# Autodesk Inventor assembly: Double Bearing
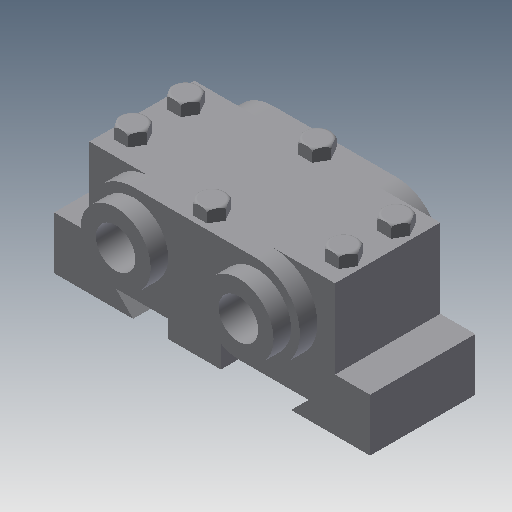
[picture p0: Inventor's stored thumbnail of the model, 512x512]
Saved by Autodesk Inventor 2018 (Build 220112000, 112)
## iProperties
Shininess: 64.0
Length Units: 11269
Angle Units: 11279
Time Units: 11290
Mass Units: 11283
Length Display Precision: 3
Angle Display Precision: 2
Created: 2002-02
Part Number: Double Bearing
Document SubType Name: Assembly
Designer: ***
Density: 0.0
Volumn: 0.0
Area: 0.0
PropertySet Name: Model Information
Control State: 0
Master: False
Checked Out: False
Author: ***
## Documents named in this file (5)
- E:\_Deepak\Inventor\Autodesk Inventor_2017_Project\Resources\Inventor_2017_tut\c12_Inv_tut_2017\c12_tut02_inv\Double Bearing.iam
- E:\_Deepak\Inventor\Autodesk Inventor_2017_Project\Resources\Inventor_2017_tut\c12_Inv_tut_2017\c12_tut02_inv\Base.ipt
- E:\_Deepak\Inventor\Autodesk Inventor_2017_Project\Resources\Inventor_2017_tut\c12_Inv_tut_2017\c12_tut02_inv\Cap.ipt
- E:\_Deepak\Inventor\Autodesk Inventor_2017_Project\Resources\Inventor_2017_tut\c12_Inv_tut_2017\c12_tut02_inv\Bushing.ipt
- E:\_Deepak\Inventor\Autodesk Inventor_2017_Project\Resources\Inventor_2017_tut\c12_Inv_tut_2017\c12_tut02_inv\Bolt.ipt
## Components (10 placed, 4 different names)
1. Base:1 — Insert:1, Insert:2
2. Cap:1 — Insert:1, Insert:2, Insert:3, Insert:4, Insert:5, Insert:6
3. Bushing:1 — Insert:3
4. Bushing:2 — Insert:4
5. Bolt:1 — Insert:5
6. Bolt:6
7. Bolt:7
8. Bolt:8
9. Bolt:5 — Insert:6
10. Bolt:9
## Component patterns: Component Pattern 1 (4 elements), Component Pattern 2 (2 elements)
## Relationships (6: Insert 6)
- Insert:1: Base:1 ↔ Cap:1
- Insert:2: Base:1 ↔ Cap:1
- Insert:3: Cap:1 ↔ Bushing:1
- Insert:4: Cap:1 ↔ Bushing:2
- Insert:5: Cap:1 ↔ Bolt:1
- Insert:6: Cap:1 ↔ Bolt:5
